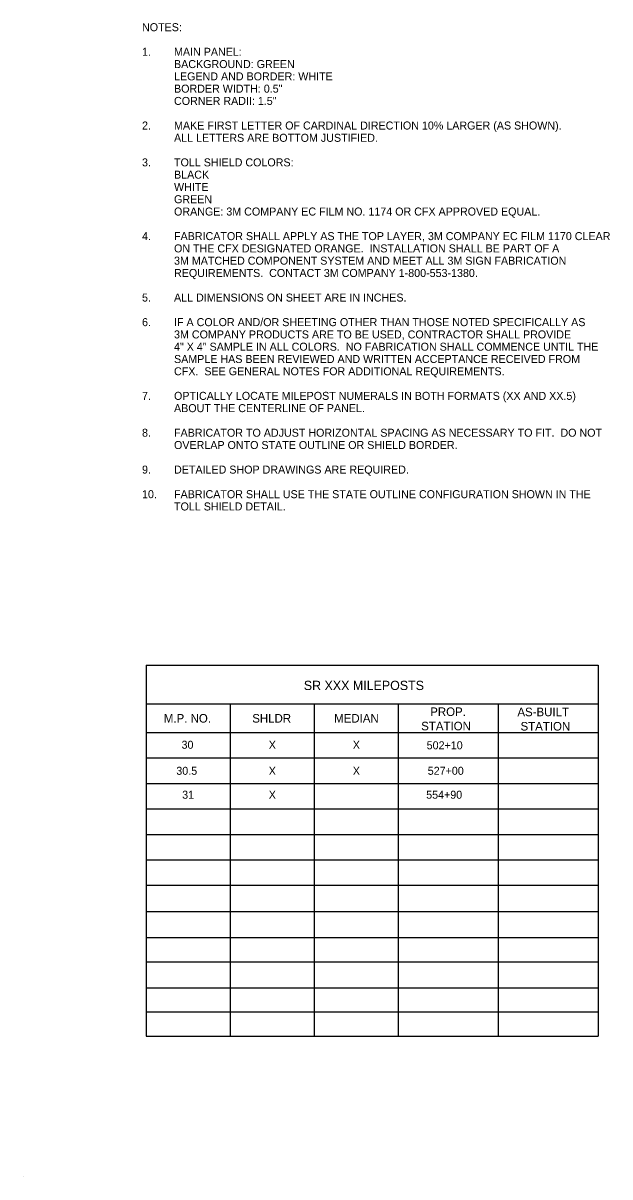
# Model space of a CAD drawing. Extents: x 56108 to 56738, y 11696 to 12112.
# Drawn here: x 56107.9 to 56313.3, y 11696.3 to 12100.1 of the extents above; entities that cross this region are included whole.
import ezdxf

# ---------------------------------------------------------------- set-up
doc = ezdxf.new("R2010")
doc.units = 0
for name, color, linetype in [('AdhocPoint_dp', 7, 'Continuous'), ('TextNotes', 7, 'Continuous'), ('TextTables', 7, 'Continuous')]:
    doc.layers.add(name, color=color, linetype=linetype)

msp = doc.modelspace()

# ---------------------------------------------------------------- linework, layer by layer
at = {"layer": 'AdhocPoint_dp'}
msp.add_line((56107.89, 11696.32), (56107.89, 11696.32), dxfattribs=at)
at = {"layer": 'TextTables'}
for p, q in [((56150.94, 11875.35), (56150.94, 11745.58)), ((56150.94, 11875.35), (56309.17, 11875.35)), ((56309.17, 11875.35), (56309.17, 11745.58)), ((56150.94, 11861.81), (56309.17, 11861.81)), ((56180.35, 11861.81), (56180.35, 11745.58)), ((56209.76, 11861.81), (56209.76, 11745.58)), ((56239.17, 11861.81), (56239.17, 11745.58)), ((56274.17, 11861.81), (56274.17, 11745.58)), ((56150.94, 11851.81), (56309.17, 11851.81)), ((56150.94, 11842.91), (56309.17, 11842.91)), ((56150.94, 11834), (56309.17, 11834)), ((56150.94, 11825.1), (56309.17, 11825.1)), ((56150.94, 11816.19), (56309.17, 11816.19)), ((56150.94, 11807.29), (56309.17, 11807.29)), ((56150.94, 11798.38), (56309.17, 11798.38)), ((56150.94, 11789.24), (56309.17, 11789.24)), ((56150.94, 11780.08), (56309.17, 11780.08)), ((56150.94, 11771.6), (56309.17, 11771.6)), ((56150.94, 11762.52), (56309.17, 11762.52)), ((56150.94, 11754.05), (56309.17, 11754.05)), ((56150.94, 11745.58), (56309.17, 11745.58))]:
    msp.add_line(p, q, dxfattribs=at)

# ---------------------------------------------------------------- texts
at = {"layer": 'TextNotes'}
for s, p in [('NOTES:', (56149.52, 12097.22)), ('1.', (56149.52, 12088.62)), ('MAIN PANEL:', (56160.72, 12088.62)), ('BACKGROUND: GREEN', (56160.72, 12084.32)), ('LEGEND AND BORDER: WHITE', (56160.72, 12080.02)), ('BORDER WIDTH: 0.5"', (56160.72, 12075.72)), ('CORNER RADII: 1.5"', (56160.72, 12071.42)), ('2.', (56149.52, 12062.82)), ('MAKE FIRST LETTER OF CARDINAL DIRECTION 10% LARGER (AS SHOWN).', (56160.72, 12062.82)), ('ALL LETTERS ARE BOTTOM JUSTIFIED.', (56160.72, 12058.52)), ('3.', (56149.52, 12049.92)), ('TOLL SHIELD COLORS:', (56160.72, 12049.92)), ('BLACK', (56160.72, 12045.62)), ('WHITE', (56160.72, 12041.32)), ('GREEN', (56160.72, 12037.02)), ('ORANGE: 3M COMPANY EC FILM NO. 1174 OR CFX APPROVED EQUAL.', (56160.72, 12032.72)), ('4.', (56149.52, 12024.12)), ('FABRICATOR SHALL APPLY AS THE TOP LAYER, 3M COMPANY EC FILM 1170 CLEAR', (56160.72, 12024.12)), ('ON THE CFX DESIGNATED ORANGE.  INSTALLATION SHALL BE PART OF A ', (56160.72, 12019.82)), ('3M MATCHED COMPONENT SYSTEM AND MEET ALL 3M SIGN FABRICATION ', (56160.72, 12015.52)), ('REQUIREMENTS.  CONTACT 3M COMPANY 1-800-553-1380.', (56160.72, 12011.22)), ('5.', (56149.52, 12002.62)), ('ALL DIMENSIONS ON SHEET ARE IN INCHES.', (56160.72, 12002.62)), ('6.', (56149.52, 11994.02)), ('IF A COLOR AND/OR SHEETING OTHER THAN THOSE NOTED SPECIFICALLY AS ', (56160.72, 11994.02)), ('3M COMPANY PRODUCTS ARE TO BE USED, CONTRACTOR SHALL PROVIDE', (56160.72, 11989.72)), ('4" X 4" SAMPLE IN ALL COLORS.  NO FABRICATION SHALL COMMENCE UNTIL THE ', (56160.72, 11985.42)), ('SAMPLE HAS BEEN REVIEWED AND WRITTEN ACCEPTANCE RECEIVED FROM', (56160.72, 11981.12)), ('CFX.  SEE GENERAL NOTES FOR ADDITIONAL REQUIREMENTS.', (56160.72, 11976.82)), ('OPTICALLY LOCATE MILEPOST NUMERALS IN BOTH FORMATS (XX AND XX.5) ', (56160.72, 11968.22)), ('7.', (56149.52, 11968.22)), ('ABOUT THE CENTERLINE OF PANEL.', (56160.72, 11963.92)), ('8.', (56149.52, 11955.32)), ('FABRICATOR TO ADJUST HORIZONTAL SPACING AS NECESSARY TO FIT.  DO NOT', (56160.72, 11955.32)), ('OVERLAP ONTO STATE OUTLINE OR SHIELD BORDER.', (56160.72, 11951.02)), ('9.', (56149.52, 11942.42)), ('DETAILED SHOP DRAWINGS ARE REQUIRED.', (56160.72, 11942.42)), ('10.', (56149.52, 11933.82)), ('FABRICATOR SHALL USE THE STATE OUTLINE CONFIGURATION SHOWN IN THE', (56160.72, 11933.82)), ('TOLL SHIELD DETAIL.', (56160.72, 11929.52))]:
    msp.add_text(s, height=2.8, dxfattribs=at).set_placement(p)
at = {"layer": 'TextTables'}
for s, height, p in [('SR XXX MILEPOSTS', 3.2524, (56206.14, 11866.68)), ('M.P. NO.', 3, (56157.16, 11855.29)), ('SHLDR', 3, (56188.09, 11855.29)), ('MEDIAN', 3, (56216.76, 11855.29)), ('PROP.', 3, (56250.38, 11857.59)), ('AS-BUILT', 3, (56280.89, 11857.51)), ('STATION', 3, (56247.22, 11852.59)), ('STATION', 3, (56281.98, 11852.51))]:
    msp.add_text(s, height=height, dxfattribs=at).set_placement(p)
for s, p in [('30', (56163.35, 11846.14)), ('X', (56193.87, 11846.14)), ('X', (56223.28, 11846.14)), ('502+10', (56249.14, 11845.95)), ('30.5', (56161.52, 11837.03)), ('X', (56193.87, 11837.03)), ('X', (56223.28, 11837.03)), ('527+00', (56249.51, 11837.03)), ('31', (56163.57, 11828.65)), ('X', (56193.87, 11828.65)), ('554+90', (56248.96, 11828.65))]:
    msp.add_text(s, height=2.8, rotation=360, dxfattribs=at).set_placement(p)

doc.saveas('drawing.dxf')
